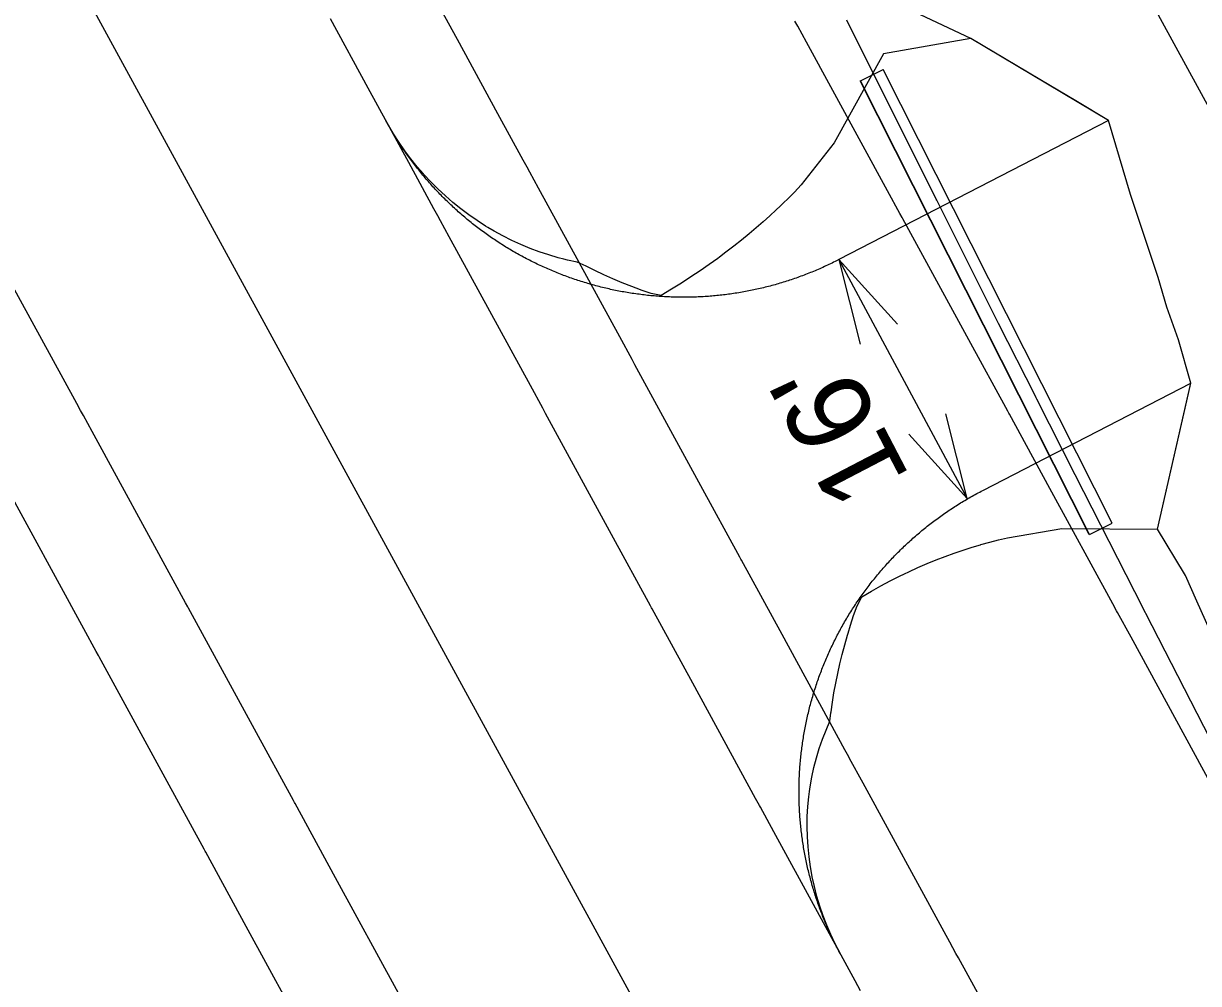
# Model space of a CAD drawing. Extents: x 1627557 to 1636561, y 783843 to 794002.
# Drawn here: x 1628135.3 to 1628204.6, y 784710.3 to 784766.9 of the extents above; entities that cross this region are included whole.
import ezdxf

# ---------------------------------------------------------------- set-up
doc = ezdxf.new("R2010")
doc.units = 0
for name, color, linetype in [('Driveway Dimensions', 7, 'Continuous'), ('R_Clearzone', 7, 'Continuous'), ('R_Ditch', 7, 'Continuous'), ('R_Driveway', 7, 'Continuous'), ('R_Driveway Slope', 7, 'Continuous'), ('R_Horz Alg', 7, 'Continuous'), ('R_Proposed Const Limits', 7, 'Continuous'), ('R_Proposed Road', 7, 'Continuous'), ('R_Proposed Shoulder', 7, 'Continuous'), ('R_ROW', 7, 'Continuous'), ('R_Water', 7, 'Continuous')]:
    doc.layers.add(name, color=color, linetype=linetype)

msp = doc.modelspace()

# ---------------------------------------------------------------- linework, layer by layer
at = {"layer": 'Driveway Dimensions'}
for p, q in [((1628183.406, 784752.994), (1628190.971, 784738.895)), ((1628183.406, 784752.994), (1628186.871, 784749.178)), ((1628183.406, 784752.994), (1628184.669, 784747.999)), ((1628190.971, 784738.895), (1628189.716, 784743.882)), ((1628190.971, 784738.895), (1628187.523, 784742.691))]:
    msp.add_line(p, q, dxfattribs=at)
at = {"layer": 'R_Clearzone'}
msp.add_lwpolyline([(1628205.428, 784721.925), (1628200.641, 784730.705), (1628199.843, 784732.168), (1628199.791, 784732.263), (1628199.565, 784732.678), (1628195.854, 784739.485), (1628193.465, 784743.866), (1628193.425, 784743.939), (1628193.37, 784744.04), (1628191.067, 784748.264), (1628187.175, 784755.402), (1628187.139, 784755.469), (1628187.007, 784755.711), (1628186.28, 784757.044), (1628181.492, 784765.824), (1628180.98, 784766.764), (1628180.812, 784767.072)], dxfattribs=at)
at = {"layer": 'R_Ditch'}
msp.add_lwpolyline([(1628206.447, 784722.481), (1628201.885, 784731.384), (1628201.128, 784732.868), (1628201.078, 784732.965), (1628200.863, 784733.386), (1628197.347, 784740.299), (1628195.09, 784744.752), (1628195.052, 784744.826), (1628195, 784744.929), (1628192.83, 784749.226), (1628189.175, 784756.493), (1628189.141, 784756.56), (1628189.017, 784756.807), (1628188.336, 784758.166), (1628183.865, 784767.117)], dxfattribs=at)
at = {"layer": 'R_Driveway'}
for points in [[(1628199.318, 784761.199), (1628183.406, 784752.994), (1628183.269, 784752.924), (1628183.18, 784752.879), (1628183.09, 784752.834), (1628183, 784752.79), (1628182.91, 784752.747), (1628182.82, 784752.704), (1628182.73, 784752.661), (1628182.639, 784752.619), (1628182.548, 784752.577), (1628182.457, 784752.536), (1628182.366, 784752.495), (1628182.274, 784752.454), (1628182.183, 784752.414), (1628182.091, 784752.375), (1628181.999, 784752.336), (1628181.906, 784752.297), (1628181.814, 784752.259), (1628181.721, 784752.222), (1628181.628, 784752.184), (1628181.535, 784752.148), (1628181.442, 784752.111), (1628181.349, 784752.076), (1628181.255, 784752.04), (1628181.162, 784752.006), (1628181.068, 784751.971), (1628180.974, 784751.937), (1628180.879, 784751.904), (1628180.785, 784751.871), (1628180.69, 784751.838), (1628180.596, 784751.806), (1628180.501, 784751.775), (1628180.406, 784751.744), (1628180.31, 784751.713), (1628180.215, 784751.683), (1628180.12, 784751.653), (1628180.024, 784751.624), (1628179.928, 784751.596), (1628179.832, 784751.567), (1628179.736, 784751.54), (1628179.64, 784751.512), (1628179.543, 784751.486), (1628179.447, 784751.459), (1628179.35, 784751.434), (1628179.254, 784751.408), (1628179.157, 784751.383), (1628179.06, 784751.359), (1628178.963, 784751.335), (1628178.865, 784751.312), (1628178.768, 784751.289), (1628178.671, 784751.267), (1628178.573, 784751.245), (1628178.475, 784751.223), (1628178.378, 784751.202), (1628178.28, 784751.182), (1628178.182, 784751.162), (1628178.084, 784751.142), (1628177.985, 784751.123), (1628177.887, 784751.105), (1628177.789, 784751.087), (1628177.69, 784751.07), (1628177.592, 784751.053), (1628177.493, 784751.036), (1628177.394, 784751.02), (1628177.296, 784751.004), (1628177.197, 784750.989), (1628177.098, 784750.975), (1628176.999, 784750.961), (1628176.9, 784750.947), (1628176.801, 784750.934), (1628176.701, 784750.922), (1628176.602, 784750.91), (1628176.503, 784750.898), (1628176.403, 784750.887), (1628176.304, 784750.876), (1628176.205, 784750.866), (1628176.105, 784750.857), (1628176.005, 784750.848), (1628175.906, 784750.839), (1628175.806, 784750.831), (1628175.706, 784750.823), (1628175.607, 784750.816), (1628175.507, 784750.81), (1628175.407, 784750.804), (1628175.307, 784750.798), (1628175.207, 784750.793), (1628175.107, 784750.788), (1628175.008, 784750.784), (1628174.908, 784750.781), (1628174.808, 784750.778), (1628174.708, 784750.775), (1628174.608, 784750.773), (1628174.508, 784750.771), (1628174.408, 784750.77), (1628174.308, 784750.77), (1628174.208, 784750.77), (1628174.108, 784750.77), (1628174.008, 784750.771), (1628173.908, 784750.772), (1628173.808, 784750.774), (1628173.708, 784750.777), (1628173.608, 784750.78), (1628173.508, 784750.783), (1628173.408, 784750.787), (1628173.308, 784750.791), (1628173.208, 784750.796), (1628173.108, 784750.802), (1628173.008, 784750.808), (1628172.909, 784750.814), (1628172.809, 784750.821), (1628172.709, 784750.828), (1628172.61, 784750.836), (1628172.51, 784750.845), (1628172.41, 784750.854), (1628172.311, 784750.863), (1628172.211, 784750.873), (1628172.112, 784750.883), (1628172.012, 784750.894), (1628171.913, 784750.905), (1628171.814, 784750.917), (1628171.714, 784750.93), (1628171.615, 784750.943), (1628171.516, 784750.956), (1628171.417, 784750.97), (1628171.318, 784750.984), (1628171.219, 784750.999), (1628171.12, 784751.014), (1628171.022, 784751.03), (1628170.923, 784751.047), (1628170.825, 784751.063), (1628170.726, 784751.081), (1628170.628, 784751.099), (1628170.529, 784751.117), (1628170.431, 784751.136), (1628170.333, 784751.155), (1628170.235, 784751.175), (1628170.137, 784751.195), (1628170.039, 784751.216), (1628169.941, 784751.237), (1628169.844, 784751.259), (1628169.746, 784751.281), (1628169.649, 784751.304), (1628169.552, 784751.327), (1628169.455, 784751.351), (1628169.358, 784751.375), (1628169.261, 784751.399), (1628169.164, 784751.425), (1628169.067, 784751.45), (1628168.971, 784751.476), (1628168.874, 784751.503), (1628168.778, 784751.53), (1628168.682, 784751.557), (1628168.586, 784751.586), (1628168.49, 784751.614), (1628168.394, 784751.643), (1628168.299, 784751.672), (1628168.203, 784751.702), (1628168.108, 784751.733), (1628168.013, 784751.764), (1628167.918, 784751.795), (1628167.823, 784751.827), (1628167.729, 784751.859), (1628167.634, 784751.892), (1628167.54, 784751.925), (1628167.446, 784751.959), (1628167.352, 784751.993), (1628167.258, 784752.028), (1628167.164, 784752.063), (1628167.071, 784752.099), (1628166.978, 784752.135), (1628166.884, 784752.171), (1628166.792, 784752.208), (1628166.699, 784752.246), (1628166.606, 784752.284), (1628166.514, 784752.322), (1628166.422, 784752.361), (1628166.33, 784752.4), (1628166.238, 784752.44), (1628166.147, 784752.48), (1628166.055, 784752.521), (1628165.964, 784752.562), (1628165.873, 784752.604), (1628165.783, 784752.646), (1628165.692, 784752.688), (1628165.602, 784752.731), (1628165.512, 784752.775), (1628165.422, 784752.819), (1628165.332, 784752.863), (1628165.243, 784752.908), (1628165.153, 784752.953), (1628165.065, 784752.999), (1628164.976, 784753.045), (1628164.887, 784753.091), (1628164.799, 784753.138), (1628164.711, 784753.186), (1628164.623, 784753.233), (1628164.536, 784753.282), (1628164.448, 784753.331), (1628164.361, 784753.38), (1628164.274, 784753.429), (1628164.188, 784753.479), (1628164.101, 784753.53), (1628164.015, 784753.581), (1628163.93, 784753.632), (1628163.844, 784753.684), (1628163.759, 784753.736), (1628163.674, 784753.789), (1628163.589, 784753.842), (1628163.504, 784753.895), (1628163.42, 784753.949), (1628163.336, 784754.003), (1628163.253, 784754.058), (1628163.169, 784754.113), (1628163.086, 784754.169), (1628163.003, 784754.225), (1628162.92, 784754.281), (1628162.838, 784754.338), (1628162.756, 784754.395), (1628162.674, 784754.453), (1628162.593, 784754.511), (1628162.512, 784754.569), (1628162.431, 784754.628), (1628162.35, 784754.687), (1628162.27, 784754.747), (1628162.19, 784754.807), (1628162.111, 784754.868), (1628162.031, 784754.928), (1628161.952, 784754.99), (1628161.873, 784755.051), (1628161.795, 784755.113), (1628161.717, 784755.176), (1628161.639, 784755.239), (1628161.562, 784755.302), (1628161.484, 784755.365), (1628161.407, 784755.429), (1628161.331, 784755.494), (1628161.255, 784755.558), (1628161.179, 784755.623), (1628161.103, 784755.689), (1628161.028, 784755.755), (1628160.953, 784755.821), (1628160.879, 784755.888), (1628160.804, 784755.955), (1628160.73, 784756.022), (1628160.657, 784756.09), (1628160.584, 784756.158), (1628160.511, 784756.226), (1628160.438, 784756.295), (1628160.366, 784756.364), (1628160.294, 784756.434), (1628160.223, 784756.504), (1628160.151, 784756.574), (1628160.081, 784756.645), (1628160.01, 784756.716), (1628159.94, 784756.787), (1628159.87, 784756.859), (1628159.801, 784756.931), (1628159.732, 784757.003), (1628159.663, 784757.076), (1628159.595, 784757.149), (1628159.527, 784757.222), (1628159.46, 784757.296), (1628159.392, 784757.37), (1628159.326, 784757.444), (1628159.259, 784757.519), (1628159.193, 784757.594), (1628159.127, 784757.67), (1628159.062, 784757.745), (1628158.997, 784757.821), (1628158.933, 784757.898), (1628158.868, 784757.975), (1628158.805, 784758.052), (1628158.741, 784758.129), (1628158.678, 784758.207), (1628158.616, 784758.284), (1628158.553, 784758.363), (1628158.492, 784758.441), (1628158.43, 784758.52), (1628158.369, 784758.599), (1628158.308, 784758.679), (1628158.248, 784758.759), (1628158.188, 784758.839), (1628158.129, 784758.919), (1628158.07, 784759), (1628158.011, 784759.081), (1628157.953, 784759.162), (1628157.895, 784759.244), (1628157.838, 784759.326), (1628157.781, 784759.408), (1628157.724, 784759.49), (1628157.668, 784759.573), (1628157.612, 784759.656), (1628157.557, 784759.739), (1628157.502, 784759.823), (1628157.447, 784759.907), (1628157.393, 784759.991), (1628157.339, 784760.075), (1628157.286, 784760.16), (1628157.233, 784760.245), (1628157.181, 784760.33), (1628157.129, 784760.415), (1628157.077, 784760.501), (1628157.026, 784760.587), (1628156.976, 784760.673), (1628156.925, 784760.76), (1628156.875, 784760.846), (1628156.826, 784760.933), (1628156.777, 784761.02), (1628156.729, 784761.108), (1628156.68, 784761.196)], [(1628183.495, 784712.016), (1628183.411, 784712.172), (1628183.364, 784712.26), (1628183.318, 784712.349), (1628183.272, 784712.438), (1628183.226, 784712.527), (1628183.181, 784712.616), (1628183.136, 784712.706), (1628183.092, 784712.795), (1628183.048, 784712.885), (1628183.005, 784712.975), (1628182.962, 784713.066), (1628182.92, 784713.156), (1628182.878, 784713.247), (1628182.836, 784713.338), (1628182.795, 784713.429), (1628182.755, 784713.521), (1628182.715, 784713.612), (1628182.675, 784713.704), (1628182.636, 784713.796), (1628182.597, 784713.888), (1628182.559, 784713.981), (1628182.521, 784714.073), (1628182.484, 784714.166), (1628182.447, 784714.259), (1628182.41, 784714.352), (1628182.374, 784714.445), (1628182.339, 784714.539), (1628182.304, 784714.632), (1628182.269, 784714.726), (1628182.235, 784714.82), (1628182.202, 784714.915), (1628182.168, 784715.009), (1628182.136, 784715.103), (1628182.104, 784715.198), (1628182.072, 784715.293), (1628182.041, 784715.388), (1628182.01, 784715.483), (1628181.98, 784715.578), (1628181.95, 784715.674), (1628181.92, 784715.769), (1628181.892, 784715.865), (1628181.863, 784715.961), (1628181.835, 784716.057), (1628181.808, 784716.153), (1628181.781, 784716.25), (1628181.754, 784716.346), (1628181.728, 784716.443), (1628181.703, 784716.539), (1628181.678, 784716.636), (1628181.653, 784716.733), (1628181.629, 784716.83), (1628181.606, 784716.927), (1628181.583, 784717.025), (1628181.56, 784717.122), (1628181.538, 784717.219), (1628181.516, 784717.317), (1628181.495, 784717.415), (1628181.475, 784717.513), (1628181.455, 784717.611), (1628181.435, 784717.709), (1628181.416, 784717.807), (1628181.397, 784717.905), (1628181.379, 784718.003), (1628181.361, 784718.102), (1628181.344, 784718.2), (1628181.327, 784718.299), (1628181.311, 784718.398), (1628181.295, 784718.496), (1628181.28, 784718.595), (1628181.265, 784718.694), (1628181.251, 784718.793), (1628181.237, 784718.892), (1628181.224, 784718.991), (1628181.212, 784719.09), (1628181.199, 784719.19), (1628181.188, 784719.289), (1628181.176, 784719.388), (1628181.165, 784719.488), (1628181.155, 784719.587), (1628181.145, 784719.687), (1628181.136, 784719.786), (1628181.127, 784719.886), (1628181.119, 784719.986), (1628181.111, 784720.085), (1628181.104, 784720.185), (1628181.097, 784720.285), (1628181.091, 784720.385), (1628181.085, 784720.484), (1628181.08, 784720.584), (1628181.075, 784720.684), (1628181.071, 784720.784), (1628181.067, 784720.884), (1628181.064, 784720.984), (1628181.061, 784721.084), (1628181.059, 784721.184), (1628181.057, 784721.284), (1628181.056, 784721.384), (1628181.055, 784721.484), (1628181.055, 784721.584), (1628181.055, 784721.684), (1628181.056, 784721.784), (1628181.057, 784721.884), (1628181.059, 784721.984), (1628181.061, 784722.084), (1628181.064, 784722.184), (1628181.067, 784722.284), (1628181.07, 784722.384), (1628181.075, 784722.484), (1628181.079, 784722.584), (1628181.085, 784722.683), (1628181.09, 784722.783), (1628181.097, 784722.883), (1628181.103, 784722.983), (1628181.11, 784723.083), (1628181.118, 784723.182), (1628181.126, 784723.282), (1628181.135, 784723.382), (1628181.144, 784723.481), (1628181.154, 784723.581), (1628181.164, 784723.68), (1628181.175, 784723.78), (1628181.186, 784723.879), (1628181.198, 784723.978), (1628181.21, 784724.077), (1628181.223, 784724.177), (1628181.236, 784724.276), (1628181.25, 784724.375), (1628181.264, 784724.474), (1628181.278, 784724.573), (1628181.294, 784724.672), (1628181.309, 784724.77), (1628181.325, 784724.869), (1628181.342, 784724.968), (1628181.359, 784725.066), (1628181.377, 784725.165), (1628181.395, 784725.263), (1628181.413, 784725.361), (1628181.433, 784725.459), (1628181.452, 784725.557), (1628181.472, 784725.655), (1628181.493, 784725.753), (1628181.514, 784725.851), (1628181.535, 784725.949), (1628181.557, 784726.046), (1628181.58, 784726.144), (1628181.603, 784726.241), (1628181.627, 784726.338), (1628181.651, 784726.435), (1628181.675, 784726.532), (1628181.7, 784726.629), (1628181.725, 784726.726), (1628181.751, 784726.822), (1628181.778, 784726.919), (1628181.805, 784727.015), (1628181.832, 784727.111), (1628181.86, 784727.207), (1628181.888, 784727.303), (1628181.917, 784727.399), (1628181.946, 784727.495), (1628181.976, 784727.59), (1628182.006, 784727.685), (1628182.037, 784727.781), (1628182.068, 784727.876), (1628182.1, 784727.97), (1628182.132, 784728.065), (1628182.165, 784728.16), (1628182.198, 784728.254), (1628182.231, 784728.348), (1628182.265, 784728.442), (1628182.3, 784728.536), (1628182.335, 784728.63), (1628182.37, 784728.723), (1628182.406, 784728.817), (1628182.442, 784728.91), (1628182.479, 784729.003), (1628182.516, 784729.096), (1628182.554, 784729.188), (1628182.592, 784729.281), (1628182.631, 784729.373), (1628182.67, 784729.465), (1628182.71, 784729.557), (1628182.75, 784729.648), (1628182.79, 784729.74), (1628182.831, 784729.831), (1628182.873, 784729.922), (1628182.915, 784730.013), (1628182.957, 784730.103), (1628183, 784730.194), (1628183.043, 784730.284), (1628183.087, 784730.374), (1628183.131, 784730.464), (1628183.176, 784730.553), (1628183.221, 784730.642), (1628183.266, 784730.731), (1628183.312, 784730.82), (1628183.358, 784730.909), (1628183.405, 784730.997), (1628183.452, 784731.085), (1628183.5, 784731.173), (1628183.548, 784731.261), (1628183.597, 784731.348), (1628183.646, 784731.435), (1628183.695, 784731.522), (1628183.745, 784731.609), (1628183.796, 784731.695), (1628183.846, 784731.782), (1628183.897, 784731.868), (1628183.949, 784731.953), (1628184.001, 784732.039), (1628184.054, 784732.124), (1628184.106, 784732.209), (1628184.16, 784732.293), (1628184.213, 784732.378), (1628184.268, 784732.462), (1628184.322, 784732.545), (1628184.377, 784732.629), (1628184.433, 784732.712), (1628184.488, 784732.795), (1628184.545, 784732.878), (1628184.601, 784732.96), (1628184.658, 784733.042), (1628184.716, 784733.124), (1628184.774, 784733.206), (1628184.832, 784733.287), (1628184.891, 784733.368), (1628184.95, 784733.449), (1628185.009, 784733.529), (1628185.069, 784733.609), (1628185.129, 784733.689), (1628185.19, 784733.768), (1628185.251, 784733.848), (1628185.313, 784733.926), (1628185.375, 784734.005), (1628185.437, 784734.083), (1628185.499, 784734.161), (1628185.563, 784734.239), (1628185.626, 784734.316), (1628185.69, 784734.393), (1628185.754, 784734.47), (1628185.819, 784734.546), (1628185.884, 784734.622), (1628185.949, 784734.698), (1628186.015, 784734.773), (1628186.081, 784734.848), (1628186.147, 784734.923), (1628186.214, 784734.997), (1628186.281, 784735.071), (1628186.349, 784735.145), (1628186.417, 784735.218), (1628186.485, 784735.291), (1628186.554, 784735.364), (1628186.623, 784735.436), (1628186.692, 784735.508), (1628186.762, 784735.58), (1628186.832, 784735.651), (1628186.903, 784735.722), (1628186.974, 784735.793), (1628187.045, 784735.863), (1628187.116, 784735.933), (1628187.188, 784736.002), (1628187.26, 784736.072), (1628187.333, 784736.14), (1628187.406, 784736.209), (1628187.479, 784736.277), (1628187.553, 784736.345), (1628187.627, 784736.412), (1628187.701, 784736.479), (1628187.776, 784736.545), (1628187.851, 784736.612), (1628187.926, 784736.677), (1628188.001, 784736.743), (1628188.077, 784736.808), (1628188.154, 784736.873), (1628188.23, 784736.937), (1628188.307, 784737.001), (1628188.384, 784737.064), (1628188.462, 784737.128), (1628188.54, 784737.19), (1628188.618, 784737.253), (1628188.696, 784737.315), (1628188.775, 784737.376), (1628188.854, 784737.438), (1628188.934, 784737.498), (1628189.013, 784737.559), (1628189.093, 784737.619), (1628189.174, 784737.678), (1628189.254, 784737.738), (1628189.335, 784737.796), (1628189.416, 784737.855), (1628189.498, 784737.913), (1628189.579, 784737.97), (1628189.661, 784738.028), (1628189.744, 784738.084), (1628189.826, 784738.141), (1628189.909, 784738.197), (1628189.992, 784738.252), (1628190.076, 784738.307), (1628190.16, 784738.362), (1628190.244, 784738.416), (1628190.328, 784738.47), (1628190.412, 784738.523), (1628190.497, 784738.576), (1628190.582, 784738.629), (1628190.668, 784738.681), (1628190.753, 784738.733), (1628190.839, 784738.784), (1628190.925, 784738.835), (1628191.011, 784738.885), (1628191.098, 784738.935), (1628191.185, 784738.985), (1628191.272, 784739.034), (1628191.359, 784739.083), (1628191.447, 784739.131), (1628191.535, 784739.179), (1628191.623, 784739.226), (1628191.711, 784739.273), (1628191.8, 784739.32), (1628191.888, 784739.366), (1628204.161, 784745.694)]]:
    msp.add_lwpolyline(points, dxfattribs=at)
at = {"layer": 'R_Driveway Slope'}
for points in [[(1628199.313, 784761.209), (1628191.191, 784766.049), (1628186.04, 784765.129), (1628183.119, 784759.884), (1628181.177, 784757.405), (1628180.788, 784756.974), (1628180.443, 784756.629), (1628180.085, 784756.279), (1628179.943, 784756.153), (1628179.715, 784755.928), (1628179.333, 784755.575), (1628178.937, 784755.22), (1628178.529, 784754.864), (1628178.106, 784754.507), (1628177.668, 784754.147), (1628177.214, 784753.787), (1628176.744, 784753.425), (1628176.371, 784753.14), (1628176.256, 784753.062), (1628175.75, 784752.697), (1628175.225, 784752.332), (1628174.68, 784751.967), (1628174.113, 784751.603), (1628173.525, 784751.239), (1628172.913, 784750.877), (1628172.322, 784750.984), (1628171.747, 784751.187), (1628171.709, 784751.201), (1628171.181, 784751.4), (1628170.625, 784751.623), (1628170.077, 784751.854), (1628169.539, 784752.096), (1628169.01, 784752.346), (1628168.489, 784752.605), (1628167.966, 784752.84), (1628167.402, 784752.962), (1628167.177, 784753.019), (1628166.842, 784753.104), (1628166.285, 784753.268), (1628165.733, 784753.451), (1628165.186, 784753.656), (1628164.645, 784753.88), (1628164.112, 784754.124), (1628163.586, 784754.387), (1628163.069, 784754.67), (1628162.691, 784754.895), (1628162.561, 784754.972), (1628162.063, 784755.292), (1628161.576, 784755.631), (1628161.102, 784755.988), (1628160.639, 784756.362), (1628160.189, 784756.753), (1628159.753, 784757.16), (1628159.331, 784757.583), (1628158.924, 784758.021), (1628158.896, 784758.053), (1628158.533, 784758.474), (1628158.157, 784758.94), (1628157.798, 784759.42), (1628157.456, 784759.913), (1628157.132, 784760.417), (1628156.826, 784760.933), (1628156.68, 784761.196)], [(1628183.495, 784712.016), (1628183.183, 784712.617), (1628182.928, 784713.16), (1628182.693, 784713.712), (1628182.479, 784714.271), (1628182.285, 784714.838), (1628182.113, 784715.412), (1628181.963, 784715.99), (1628181.835, 784716.574), (1628181.814, 784716.693), (1628181.729, 784717.161), (1628181.645, 784717.75), (1628181.585, 784718.342), (1628181.547, 784718.934), (1628181.532, 784719.527), (1628181.54, 784720.118), (1628181.572, 784720.707), (1628181.628, 784721.293), (1628181.67, 784721.607), (1628181.706, 784721.874), (1628181.808, 784722.451), (1628181.933, 784723.021), (1628182.08, 784723.584), (1628182.25, 784724.138), (1628182.442, 784724.683), (1628182.656, 784725.218), (1628182.875, 784725.745), (1628182.93, 784726.249), (1628182.94, 784726.306), (1628183.02, 784726.868), (1628183.113, 784727.43), (1628183.218, 784727.994), (1628183.335, 784728.559), (1628183.462, 784729.126), (1628183.601, 784729.694), (1628183.752, 784730.264), (1628183.915, 784730.836), (1628183.95, 784730.948), (1628184.089, 784731.41), (1628184.276, 784731.986), (1628184.476, 784732.563), (1628184.762, 784733.091), (1628185.321, 784733.42), (1628185.877, 784733.731), (1628186.43, 784734.026), (1628186.981, 784734.305), (1628187.28, 784734.447), (1628187.528, 784734.568), (1628188.072, 784734.816), (1628188.613, 784735.05), (1628189.15, 784735.271), (1628189.684, 784735.477), (1628190.214, 784735.671), (1628190.741, 784735.852), (1628191.265, 784736.021), (1628191.757, 784736.155), (1628191.785, 784736.178), (1628192.301, 784736.323), (1628192.815, 784736.457), (1628193.353, 784736.576), (1628196.561, 784737.12), (1628202.203, 784737.087), (1628203.929, 784744.65), (1628204.161, 784745.694)]]:
    msp.add_lwpolyline(points, dxfattribs=at)
at = {"layer": 'R_Horz Alg'}
msp.add_line((1628236.527, 784589.685), (1627810.308, 785371.394), dxfattribs=at)
at = {"layer": 'R_Proposed Const Limits'}
msp.add_lwpolyline([(1628208.633, 784723.673), (1628204.526, 784732.824), (1628203.844, 784734.349), (1628203.8, 784734.448), (1628202.203, 784737.087), (1628204.161, 784745.694), (1628203.445, 784748.254), (1628202.758, 784750.178), (1628202.231, 784751.927), (1628200.612, 784756.825), (1628199.318, 784761.199), (1628197.381, 784762.354), (1628195.252, 784763.629), (1628191.191, 784766.049), (1628186.222, 784768.402)], dxfattribs=at)
at = {"layer": 'R_Proposed Road'}
for points in [[(1628184.689, 784709.827), (1628184.356, 784710.436), (1628179.569, 784719.216), (1628178.772, 784720.679), (1628178.72, 784720.774), (1628178.494, 784721.189), (1628174.782, 784727.996), (1628172.394, 784732.377), (1628172.354, 784732.45), (1628172.298, 784732.551), (1628169.995, 784736.776), (1628166.103, 784743.913), (1628166.067, 784743.98), (1628165.935, 784744.222), (1628165.208, 784745.555), (1628160.421, 784754.335), (1628159.908, 784755.275), (1628159.741, 784755.583), (1628159.517, 784755.994), (1628158.028, 784758.725), (1628155.634, 784763.115), (1628153.404, 784767.204)], [(1628157.422, 784709.7), (1628153.711, 784716.507), (1628151.322, 784720.888), (1628151.282, 784720.961), (1628151.227, 784721.062), (1628148.924, 784725.287), (1628145.032, 784732.424), (1628144.996, 784732.491), (1628144.864, 784732.733), (1628144.137, 784734.066), (1628139.35, 784742.846), (1628138.837, 784743.786), (1628138.669, 784744.094), (1628138.445, 784744.505), (1628136.956, 784747.236), (1628134.563, 784751.626)]]:
    msp.add_lwpolyline(points, dxfattribs=at)
at = {"layer": 'R_Proposed Shoulder'}
for points in [[(1628192.497, 784708.041), (1628190.458, 784711.779), (1628190.314, 784712.043), (1628189.956, 784712.699), (1628189.624, 784713.309), (1628184.837, 784722.088), (1628184.04, 784723.551), (1628183.988, 784723.646), (1628183.761, 784724.061), (1628180.05, 784730.868), (1628177.661, 784735.249), (1628177.621, 784735.322), (1628177.566, 784735.423), (1628175.263, 784739.648), (1628171.371, 784746.786), (1628171.335, 784746.852), (1628171.203, 784747.094), (1628170.476, 784748.428), (1628165.689, 784757.207), (1628165.176, 784758.148), (1628165.009, 784758.455), (1628164.785, 784758.866), (1628163.295, 784761.597), (1628160.902, 784765.987), (1628158.672, 784770.076)], [(1628152.154, 784706.828), (1628148.443, 784713.635), (1628146.054, 784718.016), (1628146.014, 784718.089), (1628145.959, 784718.19), (1628143.656, 784722.414), (1628139.764, 784729.552), (1628139.728, 784729.619), (1628139.596, 784729.861), (1628138.869, 784731.194), (1628134.082, 784739.974)]]:
    msp.add_lwpolyline(points, dxfattribs=at)
at = {"layer": 'R_ROW'}
msp.add_line((1628269.98, 784643.223), (1628198.174, 784774.919), dxfattribs=at)
at = {"layer": 'R_Water'}
for p, q in [((1628184.674, 784763.541), (1628186.018, 784764.219)), ((1628199.521, 784737.444), (1628186.013, 784764.217)), ((1628199.525, 784737.447), (1628186.018, 784764.219)), ((1628198.177, 784736.766), (1628184.669, 784763.538)), ((1628198.181, 784736.769), (1628184.674, 784763.541)), ((1628198.181, 784736.769), (1628199.521, 784737.444))]:
    msp.add_line(p, q, dxfattribs=at)

# ---------------------------------------------------------------- texts
at = {"layer": 'Driveway Dimensions'}
msp.add_text("16'", height=5, rotation=117.53412, dxfattribs=at).set_placement((1628187.646, 784740.106))

doc.saveas('drawing.dxf')
